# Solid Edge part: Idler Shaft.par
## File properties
Author: Nimesh.N
Template: iso metric part.par
Last saved by: Nimesh.N
Revision: 46
Application: Solid Edge
Density: 7800.000 kg/m^3
Accuracy: 0.990
Username: Nimesh.N
Material: Steel - Free Cutting:1.0764 , 36SMn14
Face Style: Steel
Fill Style: ANSI32(Steel)
Grouping: Steel\Steel - Free Cutting ( Higher P or S content)
LibraryName: Materials-DIN
Coef. of Thermal Exp: 1.1e-05
Thermal Conductivity: 14.0
Specific Heat: 440.0
Modulus of Elasticity: 210000003072.0
Poisson's Ratio: 0.28
Yield Stress: 420000000.0
Ultimate Stress: 670000000.0
Elongation: 0.0
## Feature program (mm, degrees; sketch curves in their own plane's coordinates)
sketch for "unnamed Protrusion 1" plane through (0, 0, 0) normal (0, -1, 0) x-axis (1, 0, 0)
  circle centre (0, 0) radius 34
extrude "unnamed Protrusion 1" add finite 188 along -normal
sketch for "Bearing" plane through (0, 188, 0) normal (0, 1, 0) x-axis (0, 0, -1)
  circle centre (0, 0) radius 32.5
extrude "Bearing" add finite 23 along +normal
sketch for "End" plane through (0, 0, 0) normal (0, -1, 0) x-axis (0, 0, 1)
  circle centre (0, 0) radius 36
extrude "End" add finite 10 along +normal
sketch for "unnamed RevolvedCutout 1" plane through (0, 0, 0) normal (1, 0, 0) x-axis (0, 1, 0)
  line (133.15, 32.5) -> (130.5, 32.5)
  line (130.5, 32.5) -> (130.5, 34)
  line (130.5, 34) -> (133.15, 34)
  line (133.15, 34) -> (133.15, 32.5)
revolve "unnamed RevolvedCutout 1" cut full turn 360 deg
sketch for "Keyway" plane through (0, 85.5, 0) normal (0, 1, 0) x-axis (-1, 0, 0)
  line (-10.025, 26.5) -> (10.025, 26.5)
  line (10.025, 26.5) -> (10.025, 34)
  line (10.025, 34) -> (-10.025, 34)
  line (-10.025, 34) -> (-10.025, 26.5)
extrude "Keyway" cut finite 40 along -normal
chamfer "Chamfer_1" setback 4
chamfer "Chamfer_2" setback 3
fillet "Round_2" radius 10
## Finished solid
Body 1: solid body, 22 faces, 36 edges, 16 vertices.
  Faces by surface: plane 11, cylinder 9, cone 2
  Edges by curve: circle 18, line 14, intersection 4
Bounding box of the edges (mm): 72.000 x 221.000 x 72.000, from (-36, -10, -36) to (36, 211, 36).
Cylindrical faces by radius (mm): R10 x4, R32.5 x2, R34 x2, R36 x1
Conical faces (half-angle, radius in mm at the cone's reference point): 45 deg R32.5 x1, 45 deg R36 x1
Planar faces by outward normal: +x 1, +y 5, +z 1, -x 1, -y 3
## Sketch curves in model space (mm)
line (0, 133.15, 34) -> (0, 133.15, 32.5)
line (0, 133.15, 32.5) -> (0, 130.5, 32.5)
line (0, 130.5, 32.5) -> (0, 130.5, 34)
line (0, 130.5, 34) -> (0, 133.15, 34)
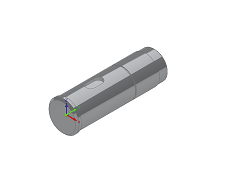
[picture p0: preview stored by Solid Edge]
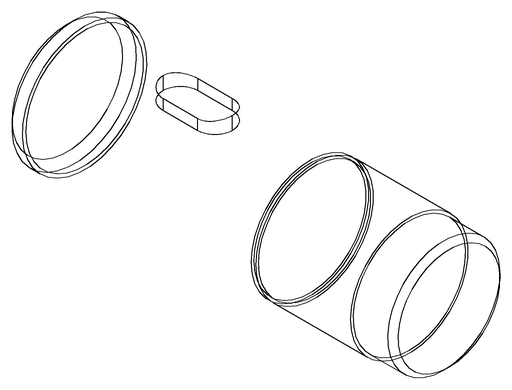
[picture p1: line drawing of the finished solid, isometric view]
